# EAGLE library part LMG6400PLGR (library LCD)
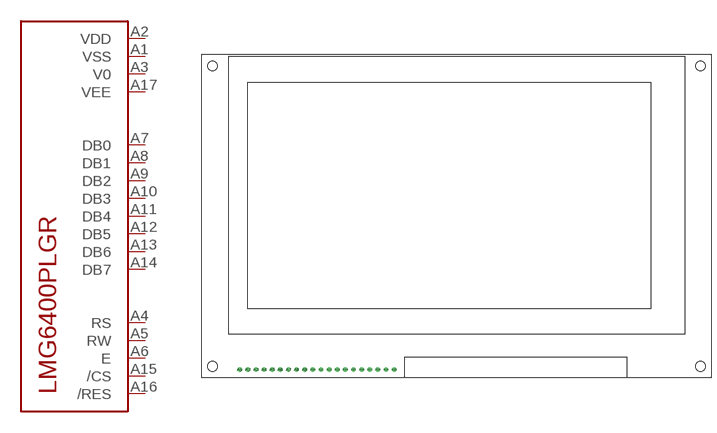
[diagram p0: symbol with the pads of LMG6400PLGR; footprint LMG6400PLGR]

Designator prefix U

## LMG6400PLGRFULL  [LMG6400PLGR]
A1  VSS  pwr
A2  VDD  pwr
A3  V0  pwr
A4  RS  in
A5  RW  in
A6  E  in
A7  DB0
A8  DB1
A9  DB2
A10  DB3
A11  DB4
A12  DB5
A13  DB6
A14  DB7
A15  /CS  in
A16  /RES  in
A17  VEE  pwr

## Footprint LMG6400PLGR (pad centres in mm)
drill 0.85 pad 1.5 round: A1 0,0; A2 2.54,0; A3 5.08,0; A4 7.62,0; A5 10.16,0; A6 12.7,0; A7 15.24,0; A8 17.78,0; A9 20.32,0; A10 22.86,0; A11 25.4,0; A12 27.94,0; A13 30.48,0; A14 33.02,0; A15 35.56,0; A16 38.1,0; A17 40.64,0; A18 43.18,0; A19 45.72,0; A20 48.26,0
hole 3.05 at -8.5,95
hole 3.05 at -8.5,1
hole 3.05 at 144,95
hole 3.05 at 144,1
